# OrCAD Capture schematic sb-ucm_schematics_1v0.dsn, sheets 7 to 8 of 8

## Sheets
7 08. Power: size C; title: SB-UCM    08. Power
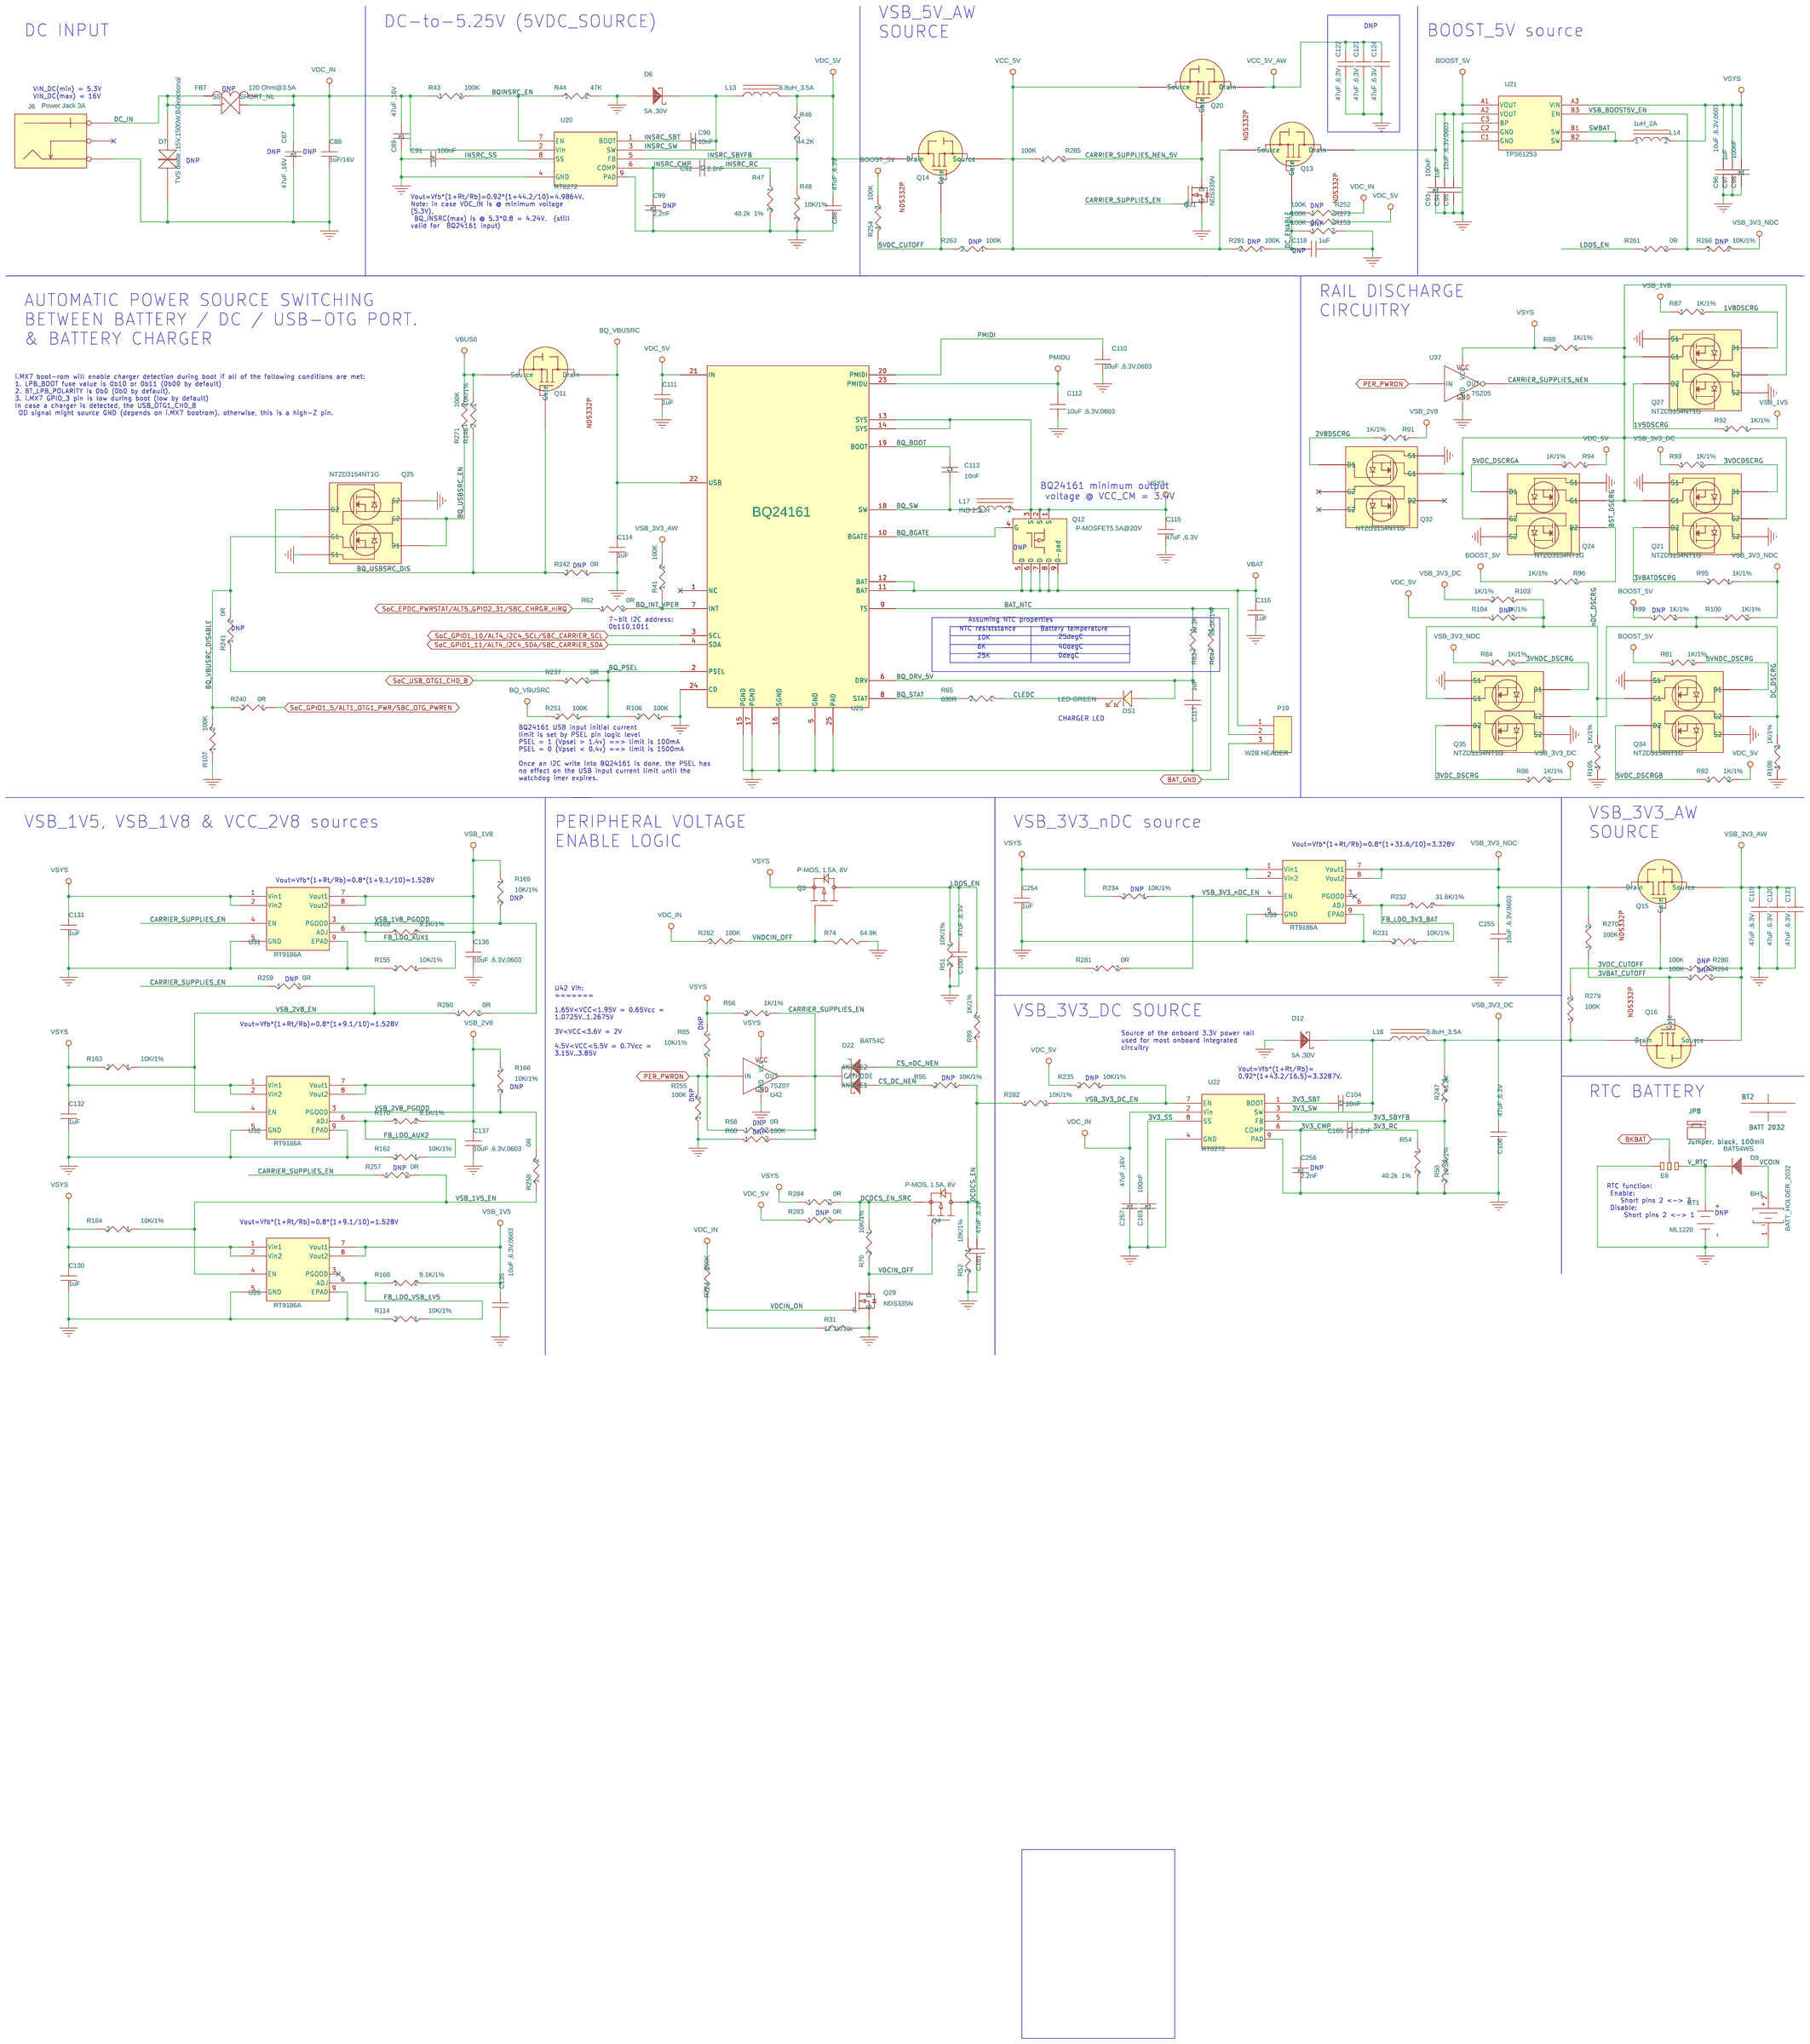
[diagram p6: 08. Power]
8 03. CompuLab CoM/SoM: size C; title: SB-UCM    03. CompuLab CoM/SoM
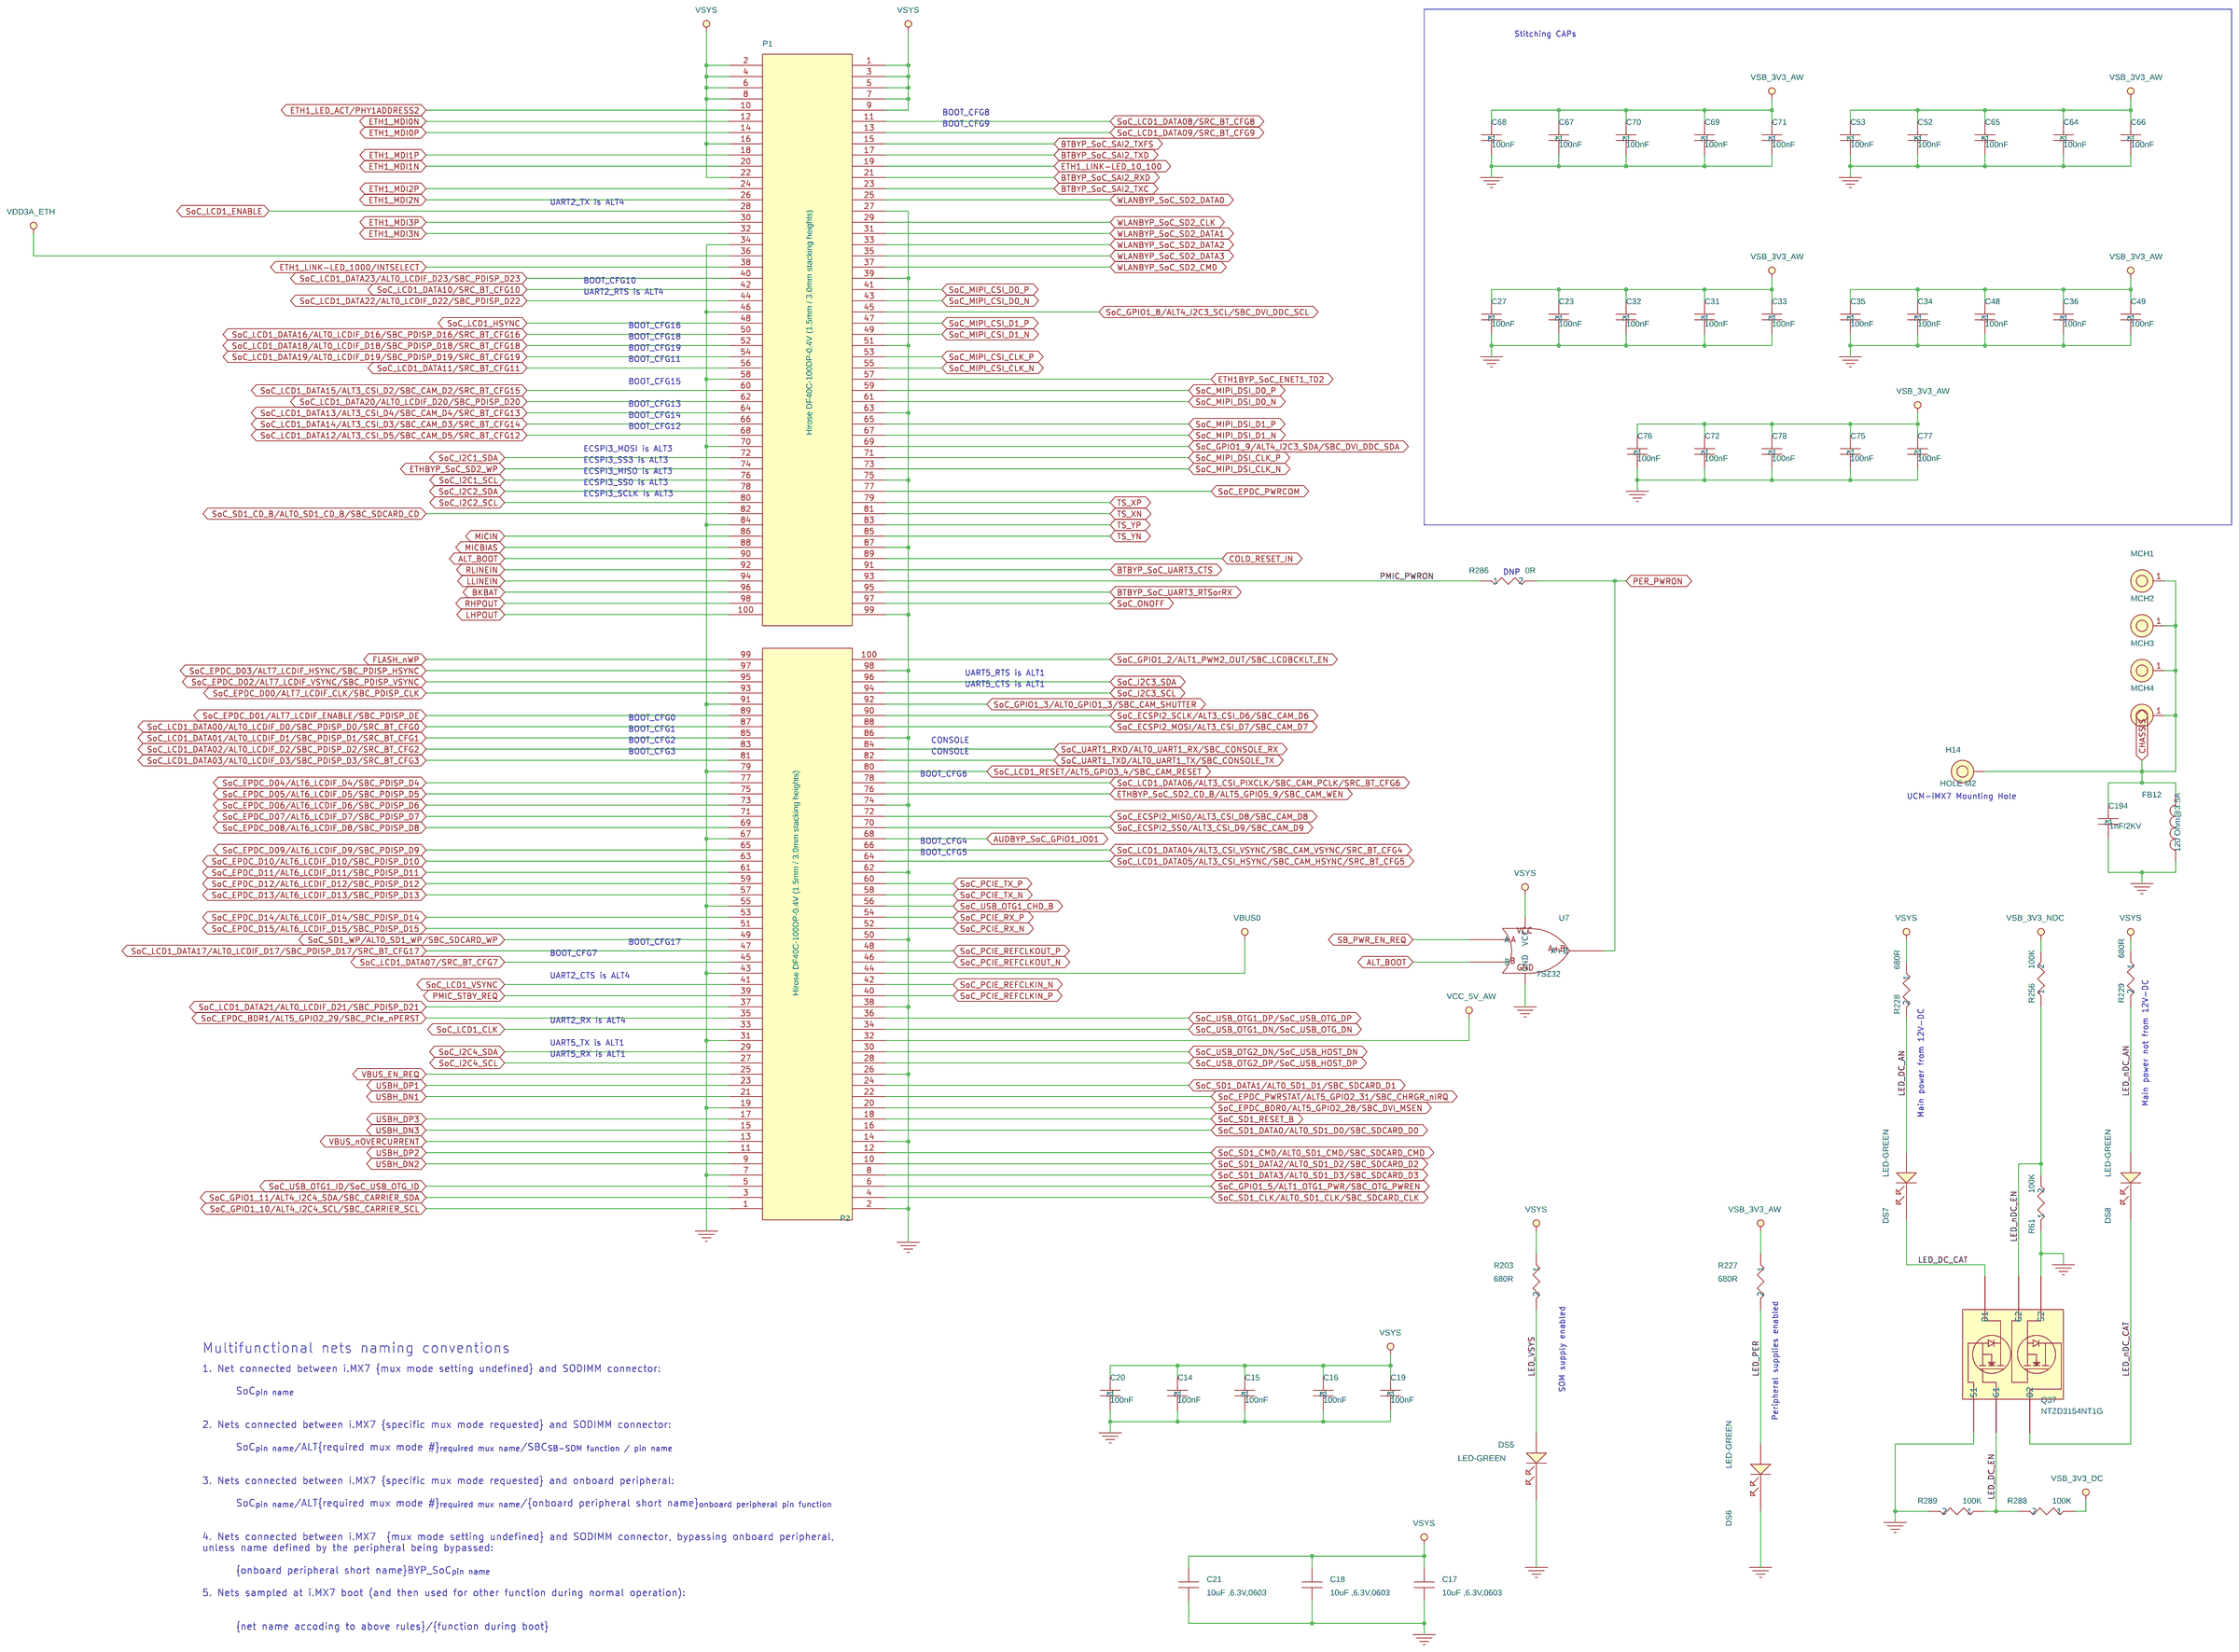
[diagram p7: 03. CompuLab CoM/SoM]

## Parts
sheet 03. CompuLab CoM/SoM
C14  100nF  [RC0402]
C15  100nF  [RC0402]
C16  100nF  [RC0402]
C17  10uF ,6.3V,0603  [C0603-08]
C18  10uF ,6.3V,0603  [C0603-08]
C19  100nF  [RC0402]
C20  100nF  [RC0402]
C21  10uF ,6.3V,0603  [C0603-08]
C23  100nF  [RC0402]
C27  100nF  [RC0402]
C31  100nF  [RC0402]
C32  100nF  [RC0402]
C33  100nF  [RC0402]
C34  100nF  [RC0402]
C35  100nF  [RC0402]
C36  100nF  [RC0402]
C48  100nF  [RC0402]
C49  100nF  [RC0402]
C52  100nF  [RC0402]
C53  100nF  [RC0402]
C64  100nF  [RC0402]
C65  100nF  [RC0402]
C66  100nF  [RC0402]
C67  100nF  [RC0402]
C68  100nF  [RC0402]
C69  100nF  [RC0402]
C70  100nF  [RC0402]
C71  100nF  [RC0402]
C72  100nF  [RC0402]
C75  100nF  [RC0402]
C76  100nF  [RC0402]
C77  100nF  [RC0402]
C78  100nF  [RC0402]
C194  1nF/2KV  [C1812-HV-2]
DS5  LED-GREEN  [LED-1206]
DS6  LED-GREEN  [LED-1206]
DS7  LED-GREEN  [LED-1206]
DS8  LED-GREEN  [LED-1206]
FB12  120 Ohm@3.5A  [FB1206]
H14  HOLE M2  [M2PAD]
MCH1  MechHole  [3,5X6,5]
MCH2  MechHole  [3,5X6,5]
MCH3  MechHole  [3,5X6,5]
MCH4  MechHole  [3,5X6,5]
P1  Hirose DF40C-100DP-0.4V (1.5mm / 3.0mm stacking heights)  [B2B04M2X50R]
P2  Hirose DF40C-100DP-0.4V (1.5mm / 3.0mm stacking heights)  [B2B04M2X50R]
Q37  NTZD3154NT1G  [SOT-563-6]
R61  100K  [RC0402]
R203  680R  [RC0402]
R227  680R  [RC0402]
R228  680R  [RC0402]
R229  680R  [RC0402]
R256  100K  [RC0402]
R286  0R  [RC0402]
R288  100K  [RC0402]
R289  100K  [RC0402]
U7  7SZ32  [SC70]
sheet 08. Power
BH1  BATT_HOLDER_2032  [BattH20mm]
BT1  ML1220  [BT1220SM]
BT2  BATT 2032
C86  47uF ,6.3V  [C0805]
C87  47uF ,16V  [C1210H2_5]
C88  1uF/16V  [RC0402]
C89  47uF ,16V  [C1210H2_5]
C90  10nF  [RC0402]
C91  100nF  [RC0402]
C92  2.2nF  [RC0402]
C93  100nF  [RC0402]
C94  1uF  [RC0402]
C95  10uF ,6.3V,0603  [C0603-08]
C96  10uF ,6.3V,0603  [C0603-08]
C97  1uF  [RC0402]
C98  100nF  [RC0402]
C99  2.2nF  [RC0402]
C100  47uF ,6.3V  [C0805]
C101  47uF ,6.3V  [C0805]
C103  100nF  [RC0402]
C104  10nF  [RC0402]
C105  2.2nF  [RC0402]
C106  47uF ,6.3V  [C0805]
C110  10uF ,6.3V,0603  [C0603-08]
C111  1uF  [RC0402]
C112  10uF ,6.3V,0603  [C0603-08]
C113  10nF  [RC0402]
C114  1uF  [RC0402]
C115  47uF ,6.3V  [C0805]
C116  1uF  [RC0402]
C117  1uF  [RC0402]
C118  1uF  [RC0402]
C119  47uF ,6.3V  [C0805]
C120  47uF ,6.3V  [C0805]
C121  47uF ,6.3V  [C0805]
C122  47uF ,6.3V  [C0805]
C123  47uF ,6.3V  [C0805]
C124  47uF ,6.3V  [C0805]
C130  1uF  [RC0402]
C131  1uF  [RC0402]
C132  1uF  [RC0402]
C135  10uF ,6.3V,0603  [C0603-08]
C136  10uF ,6.3V,0603  [C0603-08]
C137  10uF ,6.3V,0603  [C0603-08]
C254  1uF  [RC0402]
C255  10uF ,6.3V,0603  [C0603-08]
C256  2.2nF  [RC0402]
C257  47uF ,16V  [C1210H2_5]
D6  5A ,30V  [SOD-128]
D7  TVS diode ,15V,1500W,BiDirectional  [DO-214AB]
D9  BAT54WS  [SOD-323]
D12  5A ,30V  [SOD-128]
D22  BAT54C  [SOT23]
DS1  LED-GREEN  [LED-1206]
E8  JP3  [1X3THHDR]
FB7  120 Ohm@3.5A  [FB1206]
J6  Power Jack 3A  [PJ-0210-TH]
JP8  Jumper, black, 100mil  [Shunt/Jumper]
L13  6.8uH_3.5A  [IND8_2x8_2]
L14  1uH_2A  [IND-3x3_5]
L16  6.8uH_3.5A  [IND8_2x8_2]
L17  IND 2.2uH  [IND4_3x4_7SM]
P19  W2B HEADER  [1x3W2B1_5RASM]
Q3  P-MOS, 1.5A, 8V  [SOT23]
Q4  P-MOS, 1.5A, 8V  [SOT23]
Q11  NDS332P  [SOT23]
Q12  P-MOSFET5.5A@20V  [Powerpak1212-8]
Q13  NDS332P  [SOT23]
Q14  NDS332P  [SOT23]
Q15  NDS332P  [SOT23]
Q16  NDS332P  [SOT23]
Q20  NDS332P  [SOT23]
Q21  NTZD3154NT1G  [SOT-563-6]
Q24  NTZD3154NT1G  [SOT-563-6]
Q25  NTZD3154NT1G  [SOT-563-6]
Q27  NTZD3154NT1G  [SOT-563-6]
Q29  NDS335N  [SOT23]
Q31  NDS335N  [SOT23]
Q32  NTZD3154NT1G  [SOT-563-6]
Q34  NTZD3154NT1G  [SOT-563-6]
Q35  NTZD3154NT1G  [SOT-563-6]
R31  12.1K/1%  [RC0402]
R41  100K  [RC0402]
R43  100K  [RC0402]
R44  47K  [RC0402]
R46  44.2K  [RC0402]
R47  40.2k  1%  [RC0402]
R48  10K/1%  [RC0402]
R50  16.5K/1%  [RC0402]
R51  10K/1%  [RC0402]
R52  10K/1%  [RC0402]
R54  40.2k  1%  [RC0402]
R55  10K/1%  [RC0402]
R56  1K/1%  [RC0402]
R58  0R  [RC0402]
R60  100K  [RC0402]
R62  0R  [RC0402]
R63  13.3K  [RC0402]
R64  95.3K/1%  [RC0402]
R65  680R  [RC0402]
R74  64.9K  [RC0402]
R76  10K/1%  [RC0402]
R81  1K/1%  [RC0402]
R82  1K/1%  [RC0402]
R84  1K/1%  [RC0402]
R85  10K/1%  [RC0402]
R86  1K/1%  [RC0402]
R87  1K/1%  [RC0402]
R88  1K/1%  [RC0402]
R89  1K/1%  [RC0402]
R91  1K/1%  [RC0402]
R92  1K/1%  [RC0402]
R93  1K/1%  [RC0402]
R94  1K/1%  [RC0402]
R95  1K/1%  [RC0402]
R96  1K/1%  [RC0402]
R99  1K/1%  [RC0402]
R100  1K/1%  [RC0402]
R103  1K/1%  [RC0402]
R104  1K/1%  [RC0402]
R105  1K/1%  [RC0402]
R106  100K  [RC0402]
R107  100K  [RC0402]
R108  1K/1%  [RC0402]
R114  10K/1%  [RC0402]
R146  10K/1%  [RC0402]
R155  10K/1%  [RC0402]
R162  10K/1%  [RC0402]
R163  10K/1%  [RC0402]
R164  10K/1%  [RC0402]
R165  10K/1%  [RC0402]
R166  10K/1%  [RC0402]
R168  9.1K/1%  [RC0402]
R169  9.1K/1%  [RC0402]
R170  9.1K/1%  [RC0402]
R231  10K/1%  [RC0402]
R232  31.6K/1%  [RC0402]
R234  10K/1%  [RC0402]
R235  10K/1%  [RC0402]
R237  0R  [RC0402]
R240  0R  [RC0402]
R241  0R  [RC0402]
R242  0R  [RC0402]
R247  43.2K  [RC0402]
R251  100K  [RC0402]
R252  100K  [RC0402]
R253  100K  [RC0402]
R254  100K  [RC0402]
R255  100K  [RC0402]
R257  0R  [RC0402]
R258  0R  [RC0402]
R259  0R  [RC0402]
R260  0R  [RC0402]
R261  0R  [RC0402]
R262  100K  [RC0402]
R263  100K  [RC0402]
R264  100K  [RC0402]
R266  10K/1%  [RC0402]
R270  100K  [RC0402]
R271  100K  [RC0402]
R273  100K  [RC0402]
R274  100K  [RC0402]
R279  100K  [RC0402]
R280  100K  [RC0402]
R281  0R  [RC0402]
R282  10K/1%  [RC0402]
R283  0R  [RC0402]
R284  0R  [RC0402]
R285  100K  [RC0402]
R291  100K  [RC0402]
S5  SHORT_NL  [JUMPER-VIA_1]
U20  RT8272  [PSOP-8-2X2]
U21  TPS61253  [BGA-9-04-1.4x1.3]
U22  RT8272  [PSOP-8-2X2]
U25  BQ24161  [MO-220VGGD-8]
U26  RT9186A  [DFN3x3-8]
U31  RT9186A  [DFN3x3-8]
U32  RT9186A  [DFN3x3-8]
U37  7SZ05  [SC70]
U39  RT9186A  [DFN3x3-8]
U42  7SZ07  [SC70]

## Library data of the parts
C14 = 100nF,_10V,_X7R,_10%,_0402_21: CLABCONF0: = SB-UCM
C15 = 100nF,_10V,_X7R,_10%,_0402_23: CLABCONF0: = SB-UCM
C16 = 100nF,_10V,_X7R,_10%,_0402_27: CLABCONF0: = SB-UCM
C17 C95 = 10uF,6.3V,0603,20%X5R_1: CLABCONF0: = SB-UCM
C18 = 10uF,6.3V,0603,20%X5R_2: CLABCONF0: = SB-UCM
C19 C103 = 100nF,_10V,_X7R,_10%,_0402_2: CLABCONF0: = SB-UCM
C20 = 100nF,_10V,_X7R,_10%,_0402_19: CLABCONF0: = SB-UCM
C21 C96 = 10uF,6.3V,0603,20%X5R: CLABCONF0: = SB-UCM
C23 = 100nF,_10V,_X7R,_10%,_0402_10: CLABCONF0: = SB-UCM
C27 = 100nF,_10V,_X7R,_10%,_0402_13: CLABCONF0: = SB-UCM
C31 = 100nF,_10V,_X7R,_10%,_0402_15: CLABCONF0: = SB-UCM
C32 = 100nF,_10V,_X7R,_10%,_0402_16: CLABCONF0: = SB-UCM
C33 = 100nF,_10V,_X7R,_10%,_0402_17: CLABCONF0: = SB-UCM
C34 C93 = 100nF,_10V,_X7R,_10%,_0402_1: CLABCONF0: = SB-UCM
C35 = 100nF,_10V,_X7R,_10%,_0402_5: CLABCONF0: = SB-UCM
C36 = 100nF,_10V,_X7R,_10%,_0402_8: CLABCONF0: = SB-UCM
C48 = 100nF,_10V,_X7R,_10%,_0402_12: CLABCONF0: = SB-UCM
C49 = 100nF,_10V,_X7R,_10%,_0402_14: CLABCONF0: = SB-UCM
C52 = 100nF,_10V,_X7R,_10%,_0402_25: CLABCONF0: = SB-UCM
C53 = 100nF,_10V,_X7R,_10%,_0402_29: CLABCONF0: = SB-UCM
C64 = 100nF,_10V,_X7R,_10%,_0402_4: CLABCONF0: = SB-UCM
C65 = 100nF,_10V,_X7R,_10%,_0402_7: CLABCONF0: = SB-UCM
C66 = 100nF,_10V,_X7R,_10%,_0402_11: CLABCONF0: = SB-UCM
C67 = 100nF,_10V,_X7R,_10%,_0402_24: CLABCONF0: = SB-UCM
C68 = 100nF,_10V,_X7R,_10%,_0402_28: CLABCONF0: = SB-UCM
C69 C98 = 100nF,_10V,_X7R,_10%,_0402_3: CLABCONF0: = SB-UCM
C70 = 100nF,_10V,_X7R,_10%,_0402_6: CLABCONF0: = SB-UCM
C71 = 100nF,_10V,_X7R,_10%,_0402_9: CLABCONF0: = SB-UCM
C72 = 100nF,_10V,_X7R,_10%,_0402_18: CLABCONF0: = SB-UCM
C75 = 100nF,_10V,_X7R,_10%,_0402_20: CLABCONF0: = SB-UCM
C76 = 100nF,_10V,_X7R,_10%,_0402_22: CLABCONF0: = SB-UCM
C77 = 100nF,_10V,_X7R,_10%,_0402_26: CLABCONF0: = SB-UCM
C78 C91 = 100nF,_10V,_X7R,_10%,_0402: CLABCONF0: = SB-UCM
C194 = 1nF,_2KV,SMD_1812,_X7R,_10%: CLABCONF0: = SB-UCM
DS1 DS5-DS8 = LED-GREEN_1206_3: CLABCONF0: = SB-UCM
FB12 = Ferrite_bead_,_120_Ohm@3A: CLABCONF0: = SB-UCM
H14 = Hole,_Plated,_M2,_5mm._ext.: CLABCONF0: DNP
MCH1-MCH4 = Mechanical_Hole: CLABCONF0: DNP; P/N: 3X6HOL
P1 P2 = Hirose_DF40C-100DP-0.4V: CLABCONF0: = SB-UCM; P/N: 182K10004S
Q21 Q24 Q25 Q27 Q32 Q34 Q35 Q37 = MOSFET_N_DUAL_0_0.4A_20V: CLABCONF0: = SB-UCM
R61 R274 = 100K,_0402_2: CLABCONF0: = SB-UCM; P/N: 161C10031S
R203 = 47K,_0402_1: CLABCONF0: = SB-UCM; P/N: 161C68001S
R65 R227 = 47K,_0402: CLABCONF0: = SB-UCM; P/N: 161C68001S
R228 = 47K,_0402_2: CLABCONF0: = SB-UCM; P/N: 161C68001S
R229 = 47K,_0402_3: CLABCONF0: = SB-UCM; P/N: 161C68001S
R256 R291 = 100K,_0402_3: CLABCONF0: = SB-UCM; P/N: 161C10031S
R259 R286 = 0R,_0402: CLABCONF0: DNP
R288 = 100K,_0402_1: CLABCONF0: = SB-UCM; P/N: 161C10031S
R270 R289 = 100K,_0402: CLABCONF0: = SB-UCM; P/N: 161C10031S
U7 = 7SZ32_OR_sgl_SC70: CLABCONF0: = SB-UCM
BH1 = BATT_HOLDER_0: CLABCONF0: = SB-UCM
BT1 = ML1020: CLABCONF0: DNP
BT2 = BATT_2032: CLABCONF0: = SB-UCM
C86 = 47uF,6.3V,X5R_3: CLABCONF0: = SB-UCM
C87 = Cap.,_47uF,_16V,_X5R_2: CLABCONF0: DNP
C88 = 1uF,16V,0402: CLABCONF0: = SB-UCM
C89 = Cap.,_47uF,_16V,_X5R_1: CLABCONF0: = SB-UCM
C90 = 10nF,_25V,_X7R,_10%,_0402: CLABCONF0: = SB-UCM
C92 = 2.2nF,_50V,_X7R,_10%,_0402_3: CLABCONF0: = SB-UCM
C94 C97 = Cap_1uF,X5R,6.3V,0402: CLABCONF0: = SB-UCM
C99 = 2.2nF,_50V,_X7R,_10%,_0402_1: CLABCONF0: DNP
C100 = 47uF,6.3V,X5R_2: CLABCONF0: = SB-UCM
C101 = 47uF,6.3V,X5R_1: CLABCONF0: = SB-UCM
C104 = 10nF,_25V,_X7R,_10%,_0402_1: CLABCONF0: = SB-UCM
C105 = 2.2nF,_50V,_X7R,_10%,_0402_2: CLABCONF0: = SB-UCM
C106 = 47uF,6.3V,X5R: CLABCONF0: = SB-UCM
C110 = 10uF,6.3V,0603,X5R: CLABCONF0: = SB-UCM
C111 C114 C116 C117 C130-C132 C254 = 1uF,X5R,6.3V,0402: CLABCONF0: = SB-UCM
C112 = 10uF,6.3V,0603,X5R_1: CLABCONF0: = SB-UCM
C113 = 10nF,_25V,_X7R,_10%,_0402_2: CLABCONF0: = SB-UCM
C115 = Cap.,47uF,6.3V,X5R_1: CLABCONF0: = SB-UCM
C118 = 1uF,X5R,6.3V,0402: CLABCONF0: DNP
C119 = Cap.,47uF,6.3V,X5R_5: CLABCONF0: = SB-UCM
C120 = Cap.,47uF,6.3V,X5R_6: CLABCONF0: = SB-UCM
C121 = Cap.,47uF,6.3V,X5R_4: CLABCONF0: = SB-UCM
C122 = Cap.,47uF,6.3V,X5R_2: CLABCONF0: DNP
C123 = Cap.,47uF,6.3V,X5R_3: CLABCONF0: DNP
C124 = Cap.,47uF,6.3V,X5R: CLABCONF0: DNP
C135-C137 C255 = 10uF,6_0.3V,0603,20%X5R: CLABCONF0: = SB-UCM
C256 = 2.2nF,_50V,_X7R,_10%,_0402: CLABCONF0: DNP
C257 = Cap.,_47uF,_16V,_X5R: CLABCONF0: = SB-UCM
D6 D12 = Diode_Shotky,5A,30V: CLABCONF0: = SB-UCM
D7 = Diode_,TVS_,15V,1500W_0: CLABCONF0: DNP; P/N: 132D00150S
D9 = BAT54WS_0: CLABCONF0: = SB-UCM
D22 = BAT54C: CLABCONF0: = SB-UCM
E8 = HDR_1x3_100MIL_TH_JUMPER: CLABCONF0: = SB-UCM
FB7 = Ferrite_bead_,_120_Ohm@3A: CLABCONF0: DNP
J6 = Conn._DC,_TH,_3A: CLABCONF0: = SB-UCM
JP8 = Jumper,_black,_100mil: CLABCONF0: = SB-UCM
L13 L16 = IND_6.8uH_3.5A: CLABCONF0: = SB-UCM; P/N: 147A6R801S
L14 = IND_DELTA_MPL73-2R2_2.2uH_14A_1: CLABCONF0: = SB-UCM; Isat: 7; Linit: 3.3uH; P/N: 147A1R001S
L17 = IND_DELTA_MPL73-2R2_2.2uH_14A: CLABCONF0: = SB-UCM; Group: Always; Isat: 5A; P/N: 147A2R204S
P19 = TMP_142956: CLABCONF0: = SB-UCM
Q3 Q4 = P-MOS,_1.5A,_8V: CLABCONF0: = SB-UCM
Q11 Q13-Q16 Q20 = NDS332P: CLABCONF0: = SB-UCM
Q12 = MOSFET_P,_5.5A_20V: CLABCONF0: DNP
Q29 Q31 = N-MOSFET,NDS335N,100mOhm@2.5V: CLABCONF0: = SB-UCM
R31 = 12_0.1K,1%,0402,1_16W: CLABCONF0: = SB-UCM
R41 = 100K,_0402_7: CLABCONF0: = SB-UCM; P/N: 161C10031S
R43 = 100K,_0402_13: CLABCONF0: = SB-UCM; P/N: 161C10031S
R44 = 47K,_0402_1: CLABCONF0: = SB-UCM
R46 = 100K,_0402_4: CLABCONF0: = SB-UCM; P/N: 161C44221S
R47 = 40.2k_,1%_1: CLABCONF0: = SB-UCM
R48 = 10K,1%,0402,1_16W_11: CLABCONF0: = SB-UCM
R50 = 10K,1%,0402,1_16W_8: CLABCONF0: = SB-UCM; P/N: 161C16521S
R51 = 10K,1%,0402,1_16W_6: CLABCONF0: = SB-UCM
R52 = 10K,1%,0402,1_16W_1: CLABCONF0: = SB-UCM
R54 = 40.2k_,1%: CLABCONF0: = SB-UCM
R55 = 10K,1%,0402,1_16W_15: CLABCONF0: DNP
R56 = 1K,1%,0402,1_16W_11: CLABCONF0: = SB-UCM; Group: CAN
R58 = 0R,_0402_10: CLABCONF0: DNP
R60 = 100K,_0402_1: CLABCONF0: DNP; P/N: 161C10031S
R62 = 0R,_0402_2: CLABCONF0: = SB-UCM
R63 = 13.3K,_0402_tmp: CLABCONF0: = SB-UCM; P/N: 161C13321S
R64 = 4.99K,1%,0402,1_16W: CLABCONF0: = SB-UCM; P/N: 161C95321S
R74 = 64.9K,1%,0402: CLABCONF0: = SB-UCM; P/N: 161C64921S
R76 = 10K,1%,0402,1_16W_17: CLABCONF0: = SB-UCM
R81 = 1K,1%,0402,1_16W_3: CLABCONF0: = SB-UCM; Group: CAN
R82 = 1K,1%,0402,1_16W_2: CLABCONF0: = SB-UCM; Group: CAN
R84 = 1K,1%,0402,1_16W_15: CLABCONF0: = SB-UCM; Group: CAN
R85 = 10K,1%,0402,1_16W_19: CLABCONF0: DNP
R86 = 1K,1%,0402,1_16W_12: CLABCONF0: = SB-UCM; Group: CAN
R87 = 1K,1%,0402,1_16W_5: CLABCONF0: = SB-UCM; Group: CAN
R88 = 1K,1%,0402,1_16W_10: CLABCONF0: = SB-UCM; Group: CAN
R89 = 1K,1%,0402,1_16W_4: CLABCONF0: = SB-UCM; Group: CAN
R91 = 1K,1%,0402,1_16W_9: CLABCONF0: = SB-UCM; Group: CAN
R92 = 1K,1%,0402,1_16W_6: CLABCONF0: = SB-UCM; Group: CAN
R93 = 1K,1%,0402,1_16W_14: CLABCONF0: = SB-UCM; Group: CAN
R94 = 1K,1%,0402,1_16W_7: CLABCONF0: = SB-UCM; Group: CAN
R95 = 1K,1%,0402,1_16W_19: CLABCONF0: = SB-UCM; Group: CAN
R96 = 1K,1%,0402,1_16W_18: CLABCONF0: = SB-UCM; Group: CAN
R99 = 1K,1%,0402,1_16W_17: CLABCONF0: DNP; Group: CAN
R100 = 1K,1%,0402,1_16W_1: CLABCONF0: = SB-UCM; Group: CAN
R103 = 1K,1%,0402,1_16W_8: CLABCONF0: = SB-UCM; Group: CAN
R104 = 1K,1%,0402,1_16W_16: CLABCONF0: DNP; Group: CAN
R105 = 1K,1%,0402,1_16W_13: CLABCONF0: = SB-UCM; Group: CAN
R106 = 100K,_0402_14: CLABCONF0: = SB-UCM; P/N: 161C10031S
R107 = 100K,_0402_15: CLABCONF0: = SB-UCM; P/N: 161C10031S
R108 = 1K,1%,0402,1_16W: CLABCONF0: = SB-UCM; Group: CAN
R114 = 10K,1%,0402,1_16W_12: CLABCONF0: = SB-UCM
R146 = 10K,1%,0402,1_16W_14: CLABCONF0: = SB-UCM
R155 = 10K,1%,0402,1_16W_3: CLABCONF0: = SB-UCM
R162 = 10K,1%,0402,1_16W_4: CLABCONF0: = SB-UCM
R163 = 10K,1%,0402,1_16W_16: CLABCONF0: = SB-UCM
R164 = 10K,1%,0402,1_16W_10: CLABCONF0: = SB-UCM
R165 = 10K,1%,0402,1_16W_18: CLABCONF0: DNP
R166 = 10K,1%,0402,1_16W_5: CLABCONF0: DNP
R168 = 953R,1%,0402,1_16W_0_2: CLABCONF0: = SB-UCM; P/N: 161C91011S
R169 = 953R,1%,0402,1_16W_0_1: CLABCONF0: = SB-UCM; P/N: 161C91011S
R170 = 953R,1%,0402,1_16W_0: CLABCONF0: = SB-UCM; P/N: 161C91011S
R231 = 10K,1%,0402,1_16W_7: CLABCONF0: = SB-UCM
R232 = 953R,1%,0402,1_16W_0_3: CLABCONF0: = SB-UCM; P/N: 161C31621S
R234 = 10K,1%,0402,1_16W_2: CLABCONF0: DNP
R235 = 10K,1%,0402,1_16W: CLABCONF0: DNP
R237 = 0R,_0402_1: CLABCONF0: = SB-UCM
R240 = 0R,_0402_3: CLABCONF0: = SB-UCM
R241 = 0R,_0402_13: CLABCONF0: DNP
R242 = 0R,_0402_5: CLABCONF0: DNP
R247 = 100K,_0402_11: CLABCONF0: = SB-UCM; P/N: 161C43221S
R251 = 100K,_0402_22: CLABCONF0: = SB-UCM; P/N: 161C10031S
R252 = 100K,_0402_20: CLABCONF0: DNP; P/N: 161C10031S
R253 = 100K,_0402_12: CLABCONF0: DNP; P/N: 161C10031S
R254 = 100K,_0402_8: CLABCONF0: = SB-UCM; P/N: 161C10031S
R255 = 100K,_0402_10: CLABCONF0: DNP; P/N: 161C10031S
R257 = 0R,_0402_9: CLABCONF0: DNP
R258 = 0R,_0402_4: CLABCONF0: = SB-UCM
R260 = 0R,_0402_12: CLABCONF0: = SB-UCM
R261 = 0R,_0402_6: CLABCONF0: = SB-UCM
R262 = 100K,_0402_19: CLABCONF0: = SB-UCM; P/N: 161C10031S
R263 = 100K,_0402_9: CLABCONF0: DNP; P/N: 161C10031S
R264 = 100K,_0402_21: CLABCONF0: DNP; P/N: 161C10031S
R266 = 10K,1%,0402,1_16W_9: CLABCONF0: DNP
R271 = 100K,_0402_5: CLABCONF0: = SB-UCM; P/N: 161C10031S
R273 = 100K,_0402_6: CLABCONF0: = SB-UCM; P/N: 161C10031S
R279 = 100K,_0402_16: CLABCONF0: = SB-UCM; P/N: 161C10031S
R280 = 100K,_0402_17: CLABCONF0: DNP; P/N: 161C10031S
R281 = 0R,_0402_8: CLABCONF0: = SB-UCM
R282 = 10K,1%,0402,1_16W_13: CLABCONF0: = SB-UCM
R283 = 0R,_0402_11: CLABCONF0: DNP
R284 = 0R,_0402_7: CLABCONF0: = SB-UCM
R285 = 100K,_0402_18: CLABCONF0: = SB-UCM; P/N: 161C10031S
S5 = MISC_SHORT_NL: CLABCONF0: DNP
U20 U22 = RT8272,Converter,3A,24V: CLABCONF0: = SB-UCM
U21 = TPS61253: CLABCONF0: = SB-UCM; P/N: 123C15200S
U25 = ISL9011_DUAL_LDO_11: CLABCONF0: = SB-UCM; P/N: 123D4R202S
U26 U31 U32 U39 = RT9186A,LDO_,2.5-5_0.5V,500mA: CLABCONF0: = SB-UCM
U37 = 7SZ05_sgl_OD_inverter,_SC70: CLABCONF0: = SB-UCM
U42 = 7SZ07D,_buffer: CLABCONF0: = SB-UCM; P/N: 106D20070S

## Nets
1V5DSCRG: Q27.3(D2) R92.2
1V8DSCRG: Q27.6(D1) R87.2
2V8DSCRG: Q32.6(D1) R91.2
3V3_CMP: C105.1 C256.1 U22.6(COMP)
3V3_RC: C105.2 R54.1
3V3_SBT: C104.1 U22.1(BOOT)
3V3_SBYFB: R50.1 R247.2 U22.5(FB)
3V3_SS: C103.1 U22.8(SS)
3V3_SW: C104.2 D12.CATHODE L16.1 U22.3(SW)
3VBAT_CUTOFF: Q16.1(Gate) R264.1 R270.1
3VBATDSCRG: Q21.3(D2) R95.2
3VDC_CUTOFF: Q15.1(Gate) R279.2 R280.1
3VDC_DSCRG: Q35.3(D2) R86.1
3VDCDSCRG: Q21.6(D1) R93.2
3VNDC_DSCRG: Q35.6(D1) R84.2
5VDC_CUTOFF: Q14.1(Gate) R254.1 R263.2
5VDC_DSCRGA: Q24.6(D1) R94.2
5VDC_DSCRGB: Q34.3(D2) R82.1
5VNDC_DSCRG: Q34.6(D1) R81.2
GND: BH1.1(MINUS) BT1.2(NEG) C14.2 C15.2 C16.2 C17.1 C18.1 C19.2 C20.2 C21.1 C23.2 C27.2 C31.2 C32.2 C33.2 C34.2 C35.2 C36.2 C48.2 C49.2 C52.2 C53.2 C64.2 C65.2 C66.2 C67.2 C68.2 C69.2 C70.2 C71.2 C72.2 C75.2 C76.2 C77.2 C78.2 C86.2 C87.2 C88.2 C89.2 C91.2 C93.2 C94.2 C95.2 C96.2 C97.2 C98.2 C99.2 C100.2 C101.2 C103.2 C106.2 C110.1 C111.2 C112.1 C114.2 C115.2 C116.2 C117.2 C118.2 C119.2 C120.2 C121.2 C122.2 C123.2 C124.2 C130.2 C131.2 C132.2 C135.2 C136.2 C137.2 C194.2 C254.2 C255.2 C256.2 C257.2 D6.ANODE D7.ANODE D12.ANODE DS5.CATHODE DS6.CATHODE E8.1 FB12.1 J6.3 P1.27 P1.34 P1.39 P1.46 P1.51 P1.58 P1.63 P1.70 P1.75 P1.84 P1.87 P1.99 P2.2 P2.7 P2.14 P2.19 P2.26 P2.31 P2.38 P2.43 P2.50 P2.55 P2.62 P2.67 P2.74 P2.79 P2.86 P2.91 P2.98 Q21.1(S1) Q21.4(S2) Q24.1(S1) Q24.4(S2) Q25.1(S1) Q25.4(S2) Q27.1(S1) Q27.4(S2) Q29.2(S) Q31.2(S) Q32.1(S1) Q34.1(S1) Q34.4(S2) Q35.1(S1) Q35.4(S2) Q37.1(S1) Q37.4(S2) R31.1 R44.2 R47.2 R48.2 R50.2 R51.2 R52.2 R54.2 R60.1 R61.1 R64.2 R74.1 R105.1 R106.1 R107.1 R108.1 R114.2 R155.2 R162.2 R231.2 R242.1 R253.2 R255.1 R289.2 U7.3(GND) U20.4(GND) U20.9(PAD) U21.C1(GND) U21.C2(GND) U21.C3(BP) U22.4(GND) U22.9(PAD) U25.5(GND) U25.15(PGND) U25.16(SGND) U25.17(PGND) U25.24(CD) U25.25(PAD) U26.5(GND) U26.9(EPAD) U31.5(GND) U31.9(EPAD) U32.5(GND) U32.9(EPAD) U37.3(GND) U39.5(GND) U39.9(EPAD) U42.3(GND) ; also on sheet 1 4 5 6
VBAT: C116.1 P19.1 Q12.5(D) Q12.6(D) Q12.7(D) Q12.8(D) Q12.9(D-pad) U25.11(BAT) U25.12(BAT) ; also on sheet 6
VBUS0: P2.44 Q11.2(Source) R146.1 R271.2 ; also on sheet 6
VBUS_EN_REQ: P2.25 ; also on sheet 6
VBUS_nOVERCURRENT: P2.13 ; also on sheet 6
VCC_5V: Q13.2(Source) Q14.2(Source) Q20.2(Source) R263.1 R285.1 R291.2
VCC_5V_AW: C122.1 C123.1 C124.1 P2.32 Q20.3(Drain) ; also on sheet 1 4 5 6
VDD3A_ETH: P1.36 ; also on sheet 1
ALT_BOOT: P1.90 U7.2(B) ; also on sheet 4
AUDBYP_SoC_GPIO1_IO01: P2.68 ; also on sheet 1
BAT_GND: P19.3 ; also on sheet 6
BAT_NTC: P19.2 R63.1 R64.1 U25.9(TS)
BKBAT: E8.2 P1.96
BOOST_5V: C93.1 C94.1 C95.1 Q13.3(Drain) R81.1 R96.1 R99.1 R254.2 U21.A1(VOUT) U21.A2(VOUT) ; also on sheet 4 5 6
BQ_BGATE: Q12.4(G) U25.10(BGATE)
BQ_BOOT: C113.2 U25.19(BOOT)
BQ_DRV_5V: C117.1 DS1.ANODE R63.2 U25.6(DRV)
BQ_INT_VPER: R41.1 R62.2 U25.7(INT)
BQ_PSEL: R106.2 R237.2 R241.1 R251.1 U25.2(PSEL)
BQ_STAT: R65.2 U25.8(STAT)
BQ_SW: C113.1 L17.1 U25.18(SW)
BQ_USBSRC_DIS: Q11.1(Gate) Q25.3(D2) R146.2 R242.2
BQ_USBSRC_EN: Q25.5(G2) Q25.6(D1) R271.1
BQ_VBUSRC: C114.1 Q11.3(Drain) R251.2 U25.22(USB) ; also on sheet 6
BQ_VBUSRC_DISABLE: Q25.2(G1) R107.2 R240.2 R241.2
BQINSRC_EN: R43.2 R44.1 U20.7(EN)
BST_DSCRG: Q24.3(D2) R96.2
BTBYP_SoC_SAI2_RXD: P1.21 ; also on sheet 1
BTBYP_SoC_SAI2_TXC: P1.23 ; also on sheet 1
BTBYP_SoC_SAI2_TXD: P1.17 ; also on sheet 1
BTBYP_SoC_SAI2_TXFS: P1.15 ; also on sheet 1
BTBYP_SoC_UART3_CTS: P1.91 ; also on sheet 1
BTBYP_SoC_UART3_RTSorRX: P1.95 ; also on sheet 1
CARRIER_SUPPLIES_EN: D22.3(CATHODE) Q31.1(G) R56.1 R58.2 R60.2 R257.1 R259.1 U31.4(EN) U42.4(OUT)
CARRIER_SUPPLIES_NEN: Q21.2(G1) Q21.5(G2) Q24.2(G1) Q24.5(G2) Q27.2(G1) Q27.5(G2) Q32.2(G1) R88.1 U37.4(OUT)
CARRIER_SUPPLIES_NEN_5V: Q20.1(Gate) Q31.3(D) R285.2
CHASSIS: C194.1 FB12.2 H14.1 MCH1.1 MCH2.1 MCH3.1 MCH4.1 ; also on sheet 1 4 5 6
CLEDC: DS1.CATHODE R65.1
COLD_RESET_IN: P1.89 ; also on sheet 4
CS_DC_NEN: D22.1(ANODE1) R55.2
CS_nDC_NEN: D22.2(ANODE2) R89.1
DC_DSCRG: Q34.5(G2) Q35.5(G2) R99.2 R100.1 R108.2
DC_ENABLE: C118.1 Q13.1(Gate) R252.1 R253.1 R273.1 R291.1
DC_IN: D7.CATHODE FB7.1 J6.1 S5.1
DCDCS_EN: C101.1 Q4.3(D) R52.1 R55.1 R282.1
DCDCS_EN_SRC: Q4.2(S) R76.1 R283.2 R284.2
ETH1_LED_ACT/PHY1ADDRESS2: P1.10 ; also on sheet 1
ETH1_LINK-LED_10_100: P1.19 ; also on sheet 1
ETH1_LINK-LED_1000/INTSELECT: P1.38 ; also on sheet 1
ETH1_MDI0N: P1.12 ; also on sheet 1
ETH1_MDI0P: P1.14 ; also on sheet 1
ETH1_MDI1N: P1.20 ; also on sheet 1
ETH1_MDI1P: P1.18 ; also on sheet 1
ETH1_MDI2N: P1.26 ; also on sheet 1
ETH1_MDI2P: P1.24 ; also on sheet 1
ETH1_MDI3N: P1.32 ; also on sheet 1
ETH1_MDI3P: P1.30 ; also on sheet 1
ETH1BYP_SoC_ENET1_TD2: P1.57 ; also on sheet 1
ETHBYP_SoC_SD2_CD_B/ALT5_GPIO5_9/SBC_CAM_WEN: P2.76 ; also on sheet 1
ETHBYP_SoC_SD2_WP: P1.74 ; also on sheet 1
FB_LDO_3V3_BAT: R231.1 R232.1 U39.6(ADJ)
FB_LDO_AUX1: R155.1 R169.1 U31.6(ADJ)
FB_LDO_AUX2: R162.1 R170.1 U32.6(ADJ)
FB_LDO_VSB_1V5: R114.1 R168.1 U26.6(ADJ)
FLASH_nWP: P2.99 ; also on sheet 4
INSRC_CMP: C92.1 C99.1 U20.6(COMP)
INSRC_RC: C92.2 R47.1
INSRC_SBT: C90.1 U20.1(BOOT)
INSRC_SBYFB: R46.2 R48.1 U20.5(FB)
INSRC_SS: C91.1 U20.8(SS)
INSRC_SW: C90.2 D6.CATHODE L13.1 U20.3(SW)
LDOS_EN: C100.1 Q3.3(D) R51.1 R89.2 R261.1 R281.1
LED_DC_AN: DS7.ANODE R228.2
LED_DC_CAT: DS7.CATHODE Q37.6(D1)
LED_DC_EN: Q37.2(G1) R288.2 R289.1
LED_nDC_AN: DS8.ANODE R229.2
LED_nDC_CAT: DS8.CATHODE Q37.3(D2)
LED_nDC_EN: Q37.5(G2) R61.2 R256.1
LED_PER: DS6.ANODE R227.2
LED_VSYS: DS5.ANODE R203.2
LHPOUT: P1.100 ; also on sheet 6
LLINEIN: P1.94 ; also on sheet 6
MICBIAS: P1.88 ; also on sheet 6
MICIN: P1.86 ; also on sheet 6
nDC_DSCRG: Q34.2(G1) Q35.2(G1) R103.1 R104.2 R105.2
PER_PWRON: R58.1 R85.2 R255.2 R286.2 U7.4(A+B) U37.2(IN) U42.2(IN)
PMIC_PWRON: P1.93 R286.1
PMIC_STBY_REQ: P2.39 ; also on sheet 1
PMIDI: C110.2 U25.20(PMIDI)
PMIDU: C112.2 U25.23(PMIDU) ; also on sheet 6
RHPOUT: P1.98 ; also on sheet 6
RLINEIN: P1.92 ; also on sheet 6
SB_PWR_EN_REQ: U7.1(A) ; also on sheet 1
SoC_ECSPI2_MISO/ALT3_CSI_D8/SBC_CAM_D8: P2.72 ; also on sheet 1
SoC_ECSPI2_MOSI/ALT3_CSI_D7/SBC_CAM_D7: P2.88 ; also on sheet 1
SoC_ECSPI2_SCLK/ALT3_CSI_D6/SBC_CAM_D6: P2.90 ; also on sheet 1
SoC_ECSPI2_SS0/ALT3_CSI_D9/SBC_CAM_D9: P2.70 ; also on sheet 1
SoC_EPDC_BDR0/ALT5_GPIO2_28/SBC_DVI_MSEN: P2.20 ; also on sheet 1 5
SoC_EPDC_BDR1/ALT5_GPIO2_29/SBC_PCIe_nPERST: P2.35 ; also on sheet 1
SoC_EPDC_D00/ALT7_LCDIF_CLK/SBC_PDISP_CLK: P2.93 ; also on sheet 5
SoC_EPDC_D01/ALT7_LCDIF_ENABLE/SBC_PDISP_DE: P2.89 ; also on sheet 5
SoC_EPDC_D02/ALT7_LCDIF_VSYNC/SBC_PDISP_VSYNC: P2.95 ; also on sheet 5
SoC_EPDC_D03/ALT7_LCDIF_HSYNC/SBC_PDISP_HSYNC: P2.97 ; also on sheet 5
SoC_EPDC_D04/ALT6_LCDIF_D4/SBC_PDISP_D4: P2.77 ; also on sheet 5
SoC_EPDC_D05/ALT6_LCDIF_D5/SBC_PDISP_D5: P2.75 ; also on sheet 5
SoC_EPDC_D06/ALT6_LCDIF_D6/SBC_PDISP_D6: P2.73 ; also on sheet 5
SoC_EPDC_D07/ALT6_LCDIF_D7/SBC_PDISP_D7: P2.71 ; also on sheet 5
SoC_EPDC_D08/ALT6_LCDIF_D8/SBC_PDISP_D8: P2.69 ; also on sheet 5
SoC_EPDC_D09/ALT6_LCDIF_D9/SBC_PDISP_D9: P2.65 ; also on sheet 5
SoC_EPDC_D10/ALT6_LCDIF_D10/SBC_PDISP_D10: P2.63 ; also on sheet 5
SoC_EPDC_D11/ALT6_LCDIF_D11/SBC_PDISP_D11: P2.61 ; also on sheet 5
SoC_EPDC_D12/ALT6_LCDIF_D12/SBC_PDISP_D12: P2.59 ; also on sheet 5
SoC_EPDC_D13/ALT6_LCDIF_D13/SBC_PDISP_D13: P2.57 ; also on sheet 5
SoC_EPDC_D14/ALT6_LCDIF_D14/SBC_PDISP_D14: P2.53 ; also on sheet 5
SoC_EPDC_D15/ALT6_LCDIF_D15/SBC_PDISP_D15: P2.51 ; also on sheet 5
SoC_EPDC_PWRCOM: P1.77 ; also on sheet 1
SoC_EPDC_PWRSTAT/ALT5_GPIO2_31/SBC_CHRGR_nIRQ: P2.22 R62.1 ; also on sheet 1
SoC_GPIO1_2/ALT1_PWM2_OUT/SBC_LCDBCKLT_EN: P2.100 ; also on sheet 5
SoC_GPIO1_3/ALT0_GPIO1_3/SBC_CAM_SHUTTER: P2.92 ; also on sheet 1
SoC_GPIO1_5/ALT1_OTG1_PWR/SBC_OTG_PWREN: P2.6 R240.1 ; also on sheet 6
SoC_GPIO1_8/ALT4_I2C3_SCL/SBC_DVI_DDC_SCL: P1.45 ; also on sheet 1 5
SoC_GPIO1_9/ALT4_I2C3_SDA/SBC_DVI_DDC_SDA: P1.69 ; also on sheet 1 5
SoC_GPIO1_10/ALT4_I2C4_SCL/SBC_CARRIER_SCL: P2.1 U25.3(SCL) ; also on sheet 1 5 6
SoC_GPIO1_11/ALT4_I2C4_SDA/SBC_CARRIER_SDA: P2.3 U25.4(SDA) ; also on sheet 1 5 6
SoC_I2C1_SCL: P1.76 ; also on sheet 1
SoC_I2C1_SDA: P1.72 ; also on sheet 1
SoC_I2C2_SCL: P1.80 ; also on sheet 1
SoC_I2C2_SDA: P1.78 ; also on sheet 1
SoC_I2C3_SCL: P2.94 ; also on sheet 1
SoC_I2C3_SDA: P2.96 ; also on sheet 1
SoC_I2C4_SCL: P2.27 ; also on sheet 1
SoC_I2C4_SDA: P2.29 ; also on sheet 1
SoC_LCD1_CLK: P2.33 ; also on sheet 1
SoC_LCD1_DATA00/ALT0_LCDIF_D0/SBC_PDISP_D0/SRC_BT_CFG0: P2.87 ; also on sheet 5
SoC_LCD1_DATA01/ALT0_LCDIF_D1/SBC_PDISP_D1/SRC_BT_CFG1: P2.85 ; also on sheet 5
SoC_LCD1_DATA02/ALT0_LCDIF_D2/SBC_PDISP_D2/SRC_BT_CFG2: P2.83 ; also on sheet 5
SoC_LCD1_DATA03/ALT0_LCDIF_D3/SBC_PDISP_D3/SRC_BT_CFG3: P2.81 ; also on sheet 5
SoC_LCD1_DATA04/ALT3_CSI_VSYNC/SBC_CAM_VSYNC/SRC_BT_CFG4: P2.66 ; also on sheet 1
SoC_LCD1_DATA05/ALT3_CSI_HSYNC/SBC_CAM_HSYNC/SRC_BT_CFG5: P2.64 ; also on sheet 1
SoC_LCD1_DATA06/ALT3_CSI_PIXCLK/SBC_CAM_PCLK/SRC_BT_CFG6: P2.78 ; also on sheet 1
SoC_LCD1_DATA07/SRC_BT_CFG7: P2.45 ; also on sheet 1
SoC_LCD1_DATA08/SRC_BT_CFG8: P1.11 ; also on sheet 1
SoC_LCD1_DATA09/SRC_BT_CFG9: P1.13 ; also on sheet 1
SoC_LCD1_DATA10/SRC_BT_CFG10: P1.42 ; also on sheet 1
SoC_LCD1_DATA11/SRC_BT_CFG11: P1.56 ; also on sheet 1
SoC_LCD1_DATA12/ALT3_CSI_D5/SBC_CAM_D5/SRC_BT_CFG12: P1.68 ; also on sheet 1
SoC_LCD1_DATA13/ALT3_CSI_D4/SBC_CAM_D4/SRC_BT_CFG13: P1.64 ; also on sheet 1
SoC_LCD1_DATA14/ALT3_CSI_D3/SBC_CAM_D3/SRC_BT_CFG14: P1.66 ; also on sheet 1
SoC_LCD1_DATA15/ALT3_CSI_D2/SBC_CAM_D2/SRC_BT_CFG15: P1.60 ; also on sheet 1
SoC_LCD1_DATA16/ALT0_LCDIF_D16/SBC_PDISP_D16/SRC_BT_CFG16: P1.50 ; also on sheet 5
SoC_LCD1_DATA17/ALT0_LCDIF_D17/SBC_PDISP_D17/SRC_BT_CFG17: P2.47 ; also on sheet 5
SoC_LCD1_DATA18/ALT0_LCDIF_D18/SBC_PDISP_D18/SRC_BT_CFG18: P1.52 ; also on sheet 5
SoC_LCD1_DATA19/ALT0_LCDIF_D19/SBC_PDISP_D19/SRC_BT_CFG19: P1.54 ; also on sheet 5
SoC_LCD1_DATA20/ALT0_LCDIF_D20/SBC_PDISP_D20: P1.62 ; also on sheet 5
SoC_LCD1_DATA21/ALT0_LCDIF_D21/SBC_PDISP_D21: P2.37 ; also on sheet 5
SoC_LCD1_DATA22/ALT0_LCDIF_D22/SBC_PDISP_D22: P1.44 ; also on sheet 5
SoC_LCD1_DATA23/ALT0_LCDIF_D23/SBC_PDISP_D23: P1.40 ; also on sheet 5
SoC_LCD1_ENABLE: P1.28 ; also on sheet 1
SoC_LCD1_HSYNC: P1.48 ; also on sheet 1
SoC_LCD1_RESET/ALT5_GPIO3_4/SBC_CAM_RESET: P2.80 ; also on sheet 1
SoC_LCD1_VSYNC: P2.41 ; also on sheet 1
SoC_MIPI_CSI_CLK_N: P1.55 ; also on sheet 1
SoC_MIPI_CSI_CLK_P: P1.53 ; also on sheet 1
SoC_MIPI_CSI_D0_N: P1.43 ; also on sheet 1
SoC_MIPI_CSI_D0_P: P1.41 ; also on sheet 1
SoC_MIPI_CSI_D1_N: P1.49 ; also on sheet 1
SoC_MIPI_CSI_D1_P: P1.47 ; also on sheet 1
SoC_MIPI_DSI_CLK_N: P1.73 ; also on sheet 5
SoC_MIPI_DSI_CLK_P: P1.71 ; also on sheet 5
SoC_MIPI_DSI_D0_N: P1.61 ; also on sheet 5
SoC_MIPI_DSI_D0_P: P1.59 ; also on sheet 5
SoC_MIPI_DSI_D1_N: P1.67 ; also on sheet 5
SoC_MIPI_DSI_D1_P: P1.65 ; also on sheet 5
SoC_ONOFF: P1.97 ; also on sheet 4
SoC_PCIE_REFCLKIN_N: P2.42 ; also on sheet 1 6
SoC_PCIE_REFCLKIN_P: P2.40 ; also on sheet 1 6
SoC_PCIE_REFCLKOUT_N: P2.46 ; also on sheet 6
SoC_PCIE_REFCLKOUT_P: P2.48 ; also on sheet 6
SoC_PCIE_RX_N: P2.52 ; also on sheet 6
SoC_PCIE_RX_P: P2.54 ; also on sheet 6
SoC_PCIE_TX_N: P2.58 ; also on sheet 6
SoC_PCIE_TX_P: P2.60 ; also on sheet 6
SoC_SD1_CD_B/ALT0_SD1_CD_B/SBC_SDCARD_CD: P1.82 ; also on sheet 4
SoC_SD1_CLK/ALT0_SD1_CLK/SBC_SDCARD_CLK: P2.4 ; also on sheet 4
SoC_SD1_CMD/ALT0_SD1_CMD/SBC_SDCARD_CMD: P2.12 ; also on sheet 4
SoC_SD1_DATA0/ALT0_SD1_D0/SBC_SDCARD_D0: P2.16 ; also on sheet 4
SoC_SD1_DATA1/ALT0_SD1_D1/SBC_SDCARD_D1: P2.24 ; also on sheet 4
SoC_SD1_DATA2/ALT0_SD1_D2/SBC_SDCARD_D2: P2.10 ; also on sheet 4
SoC_SD1_DATA3/ALT0_SD1_D3/SBC_SDCARD_D3: P2.8 ; also on sheet 4
SoC_SD1_RESET_B: P2.18 ; also on sheet 1
SoC_SD1_WP/ALT0_SD1_WP/SBC_SDCARD_WP: P2.49 ; also on sheet 1
SoC_UART1_RXD/ALT0_UART1_RX/SBC_CONSOLE_RX: P2.84 ; also on sheet 4
SoC_UART1_TXD/ALT0_UART1_TX/SBC_CONSOLE_TX: P2.82 ; also on sheet 4
SoC_USB_OTG1_CHD_B: P2.56 R237.1
SoC_USB_OTG1_DN/SoC_USB_OTG_DN: P2.34 ; also on sheet 6
SoC_USB_OTG1_DP/SoC_USB_OTG_DP: P2.36 ; also on sheet 6
SoC_USB_OTG1_ID/SoC_USB_OTG_ID: P2.5 ; also on sheet 6
SoC_USB_OTG2_DN/SoC_USB_HOST_DN: P2.30 ; also on sheet 1
SoC_USB_OTG2_DP/SoC_USB_HOST_DP: P2.28 ; also on sheet 1
SWBAT: L14.1 U21.B1(SW) U21.B2(SW)
TS_XN: P1.81 ; also on sheet 1 5
TS_XP: P1.79 ; also on sheet 1 5
TS_YN: P1.85 ; also on sheet 1 5
TS_YP: P1.83 ; also on sheet 1 5
USBH_DN1: P2.21 ; also on sheet 6
USBH_DN2: P2.9 ; also on sheet 6
USBH_DN3: P2.15 ; also on sheet 6
USBH_DP1: P2.23 ; also on sheet 6
USBH_DP2: P2.11 ; also on sheet 6
USBH_DP3: P2.17 ; also on sheet 6
V_RTC: BT1.1(POS) D9.CATHODE E8.3
VCOIN: BH1.2(PLUS) D9.ANODE
VDC_5V: C86.1 C111.1 L13.2 Q14.3(Drain) R46.1 R82.2 R94.1 R104.1 R235.2 R273.2 R283.1 U25.21(IN)
VDC_IN: C87.1 C88.1 C89.1 C257.1 FB7.2 R43.1 R252.2 R262.2 R274.2 S5.2 U20.2(Vin) U22.2(Vin)
VDCIN_OFF: Q4.1(G) Q29.3(D) R76.2
VDCIN_ON: Q29.1(G) R31.2 R274.1
VNDCIN_OFF: Q3.1(G) R74.2 R262.1
VSB_1V5: C135.1 R92.1 R168.2 U26.7(Vout1) U26.8(Vout2) ; also on sheet 1 6
VSB_1V5_EN: R164.1 R257.2 R258.1 U26.4(EN)
VSB_1V8: C136.1 R87.1 R165.1 R169.2 U31.7(Vout1) U31.8(Vout2) ; also on sheet 1
VSB_1V8_PGOOD: R165.2 R260.2 U31.3(PGOOD)
VSB_2V8: C137.1 R91.1 R166.1 R170.2 U32.7(Vout1) U32.8(Vout2) ; also on sheet 1
VSB_2V8_EN: R163.1 R259.2 R260.1 U32.4(EN)
VSB_2V8_PGOOD: R166.2 R258.2 U32.3(PGOOD)
VSB_3V3_AW: C23.1 C27.1 C31.1 C32.1 C33.1 C34.1 C35.1 C36.1 C48.1 C49.1 C52.1 C53.1 C64.1 C65.1 C66.1 C67.1 C68.1 C69.1 C70.1 C71.1 C72.1 C75.1 C76.1 C77.1 C78.1 C119.1 C120.1 C121.1 Q15.2(Source) Q16.2(Source) R41.2 R227.1 R264.2 R280.2 ; also on sheet 1 4 5 6
VSB_3V3_DC: C106.1 L16.2 Q16.3(Drain) R86.2 R93.1 R103.2 R247.1 R279.1 R288.1
VSB_3V3_DC_EN: R235.1 R282.2 U22.7(EN)
VSB_3V3_nDC: C255.1 Q15.3(Drain) R84.1 R95.1 R100.2 R232.2 R256.2 R266.2 R270.2 U39.7(Vout1) U39.8(Vout2) ; also on sheet 4
VSB_3V3_nDC_EN: R234.1 R281.2 U39.4(EN)
VSB_BOOST5V_EN: R261.2 R266.1 U21.B3(EN)
VSYS: C14.1 C15.1 C16.1 C17.2 C18.2 C19.1 C20.1 C21.2 C96.1 C97.1 C98.1 C115.1 C130.1 C131.1 C132.1 C254.1 L14.2 L17.2 P1.1 P1.2 P1.3 P1.4 P1.5 P1.6 P1.7 P1.8 P1.9 P1.16 P1.22 Q3.2(S) Q12.1(S) Q12.2(S) Q12.3(S) R56.2 R85.1 R88.2 R163.2 R164.2 R203.1 R228.1 R229.1 R234.2 R284.1 U7.5(VCC) U21.A3(VIN) U25.13(SYS) U25.14(SYS) U26.1(Vin1) U26.2(Vin2) U31.1(Vin1) U31.2(Vin2) U32.1(Vin1) U32.2(Vin2) U37.5(VCC) U39.1(Vin1) U39.2(Vin2) U42.5(VCC) ; also on sheet 4 6
WLANBYP_SoC_SD2_CLK: P1.29 ; also on sheet 1
WLANBYP_SoC_SD2_CMD: P1.37 ; also on sheet 1
WLANBYP_SoC_SD2_DATA0: P1.25 ; also on sheet 1
WLANBYP_SoC_SD2_DATA1: P1.31 ; also on sheet 1
WLANBYP_SoC_SD2_DATA2: P1.33 ; also on sheet 1
WLANBYP_SoC_SD2_DATA3: P1.35 ; also on sheet 1

Not connected (* = marked no-connect by the designer): J6 2*; Q32 3(D2)* 4(S2)* 5(G2)*; U25 1(NC)*; U26 3(PGOOD)*; U39 3(PGOOD)*

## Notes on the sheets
sheet 7
- VSB_5V_AW
  SOURCE
- DC-to-5.25V (5VDC_SOURCE)
- DC INPUT
- DNP
- BOOST_5V source
- VIN_DC(min) = 5.3V
  VIN_DC(max) = 16V
- DNP
- DNP
- DNP
- DNP
- Vout=Vfb*(1+Rt/Rb)=0.92*(1+44.2/10)=4.9864V.
  Note: in case VDC_IN is @ minimum voltage
  (5.3V),
   BQ_INSRC(max) is @ 5.3*0.8 = 4.24V,  (still
  valid for  BQ24161 input)
- DNP
- DNP
- DNP
- DNP
- DNP
- DNP
- DNP
- RAIL DISCHARGE
  CIRCUITRY
- AUTOMATIC POWER SOURCE SWITCHING
  BETWEEN BATTERY / DC / USB-OTG PORT.
  & BATTERY CHARGER
- i.MX7 boot-rom will enable charger detection during boot if all of the following conditions are met:
  1. LPB_BOOT fuse value is 0b10 or 0b11 (0b00 by default)
  2. BT_LPB_POLARITY is 0b0 (0b0 by default).
  3. i.MX7 GPIO_3 pin is low during boot (low by default)
  In case a charger is detected, the USB_OTG1_CHD_B
   OD signal might source GND (depends on i.MX7 bootrom). otherwise, this is a high-Z pin.
- BQ24161 minimum output
   voltage @ VCC_CM = 3.4V
- DNP
- DNP
- DNP
- DNP
- 7-bit I2C address:
  0b110,1011
- Assuming NTC properties
- DNP
- NTC resiststance
- 10K
- Battery temperature
- 25degC
- 6K
- 40degC
- 25K
- 0degC
- CHARGER LED
- BQ24161 USB input initial current
  limit is set by PSEL pin logic level
  PSEL = 1 (Vpsel > 1.4v) ==> limit is 100mA
  PSEL = 0 (Vpsel < 0.4v) ==> limit is 1500mA
  Once an I2C write into BQ24161 is done, the PSEL has
  no effect on the USB input current limit until the
  watchdog imer expires.
- VSB_3V3_AW
  SOURCE
- VSB_1V5, VSB_1V8 & VCC_2V8 sources
- PERIPHERAL VOLTAGE
  ENABLE LOGIC
- VSB_3V3_nDC source
- Vout=Vfb*(1+Rt/Rb)=0.8*(1+31.6/10)=3.328V
- Vout=Vfb*(1+Rt/Rb)=0.8*(1+9.1/10)=1.528V
- DNP
- DNP
- DNP
- DNP
- DNP
- U42 Vih:
  =======
  1.65V<VCC<1.95V = 0.65Vcc =
  1.0725V..1.2675V
  3V<VCC<3.6V = 2V
  4.5V<VCC<5.5V = 0.7Vcc =
  3.15V..3.85V
- VSB_3V3_DC SOURCE
- Vout=Vfb*(1+Rt/Rb)=0.8*(1+9.1/10)=1.528V
- DNP
- Source of the onboard 3.3V power rail
  used for most onboard integrated
  circuitry
- Vout=Vfb*(1+Rt/Rb)=
  0.92*(1+43.2/16.5)=3.3287V.
- DNP
- DNP
- DNP
- RTC BATTERY
- DNP
- DNP
- DNP
- DNP
- DNP
- RTC function:
   Enable:
      Short pins 2 <-> 3
   Disable:
       Short pins 2 <-> 1
- Vout=Vfb*(1+Rt/Rb)=0.8*(1+9.1/10)=1.528V
- DNP
- DNP
sheet 8
- Stitching CAPs
- BOOT_CFG8
- BOOT_CFG9
- UART2_TX is ALT4
- BOOT_CFG10
- UART2_RTS is ALT4
- BOOT_CFG16
- BOOT_CFG18
- BOOT_CFG19
- BOOT_CFG11
- BOOT_CFG15
- BOOT_CFG13
- BOOT_CFG12
- BOOT_CFG14
- ECSPI3_MOSI is ALT3
- ECSPI3_SS3 is ALT3
- ECSPI3_MISO is ALT3
- ECSPI3_SCLK is ALT3
- ECSPI3_SS0 is ALT3
- DNP
- UART5_RTS is ALT1
- UART5_CTS is ALT1
- BOOT_CFG0
- BOOT_CFG1
- BOOT_CFG2
- CONSOLE
- BOOT_CFG3
- CONSOLE
- BOOT_CFG6
- UCM-iMX7 Mounting Hole
- BOOT_CFG4
- BOOT_CFG5
- BOOT_CFG17
- BOOT_CFG7
- UART2_CTS is ALT4
- UART2_RX is ALT4
- UART5_TX is ALT1
- UART5_RX is ALT1
- Main power not from 12V-DC
- Main power from 12V-DC
- Multifunctional nets naming conventions
- 1. Net connected between i.MX7 {mux mode setting undefined} and SODIMM connector:
- SoC_{pin name}
- SOM supply enabled
- 2. Nets connected between i.MX7 {specific mux mode requested} and SODIMM connector:
- Peripheral supplies enabled
- SoC_{pin name}/ALT{required mux mode #}_{required mux name}/SBC_{SB-SOM function / pin name}
- 3. Nets connected between i.MX7 {specific mux mode requested} and onboard peripheral:
- SoC_{pin name}/ALT{required mux mode #}_{required mux name}/{onboard peripheral short name}_{onboard peripheral pin function}
- 4. Nets connected between i.MX7  {mux mode setting undefined} and SODIMM connector, bypassing onboard peripheral,
  unless name defined by the peripheral being bypassed:
- {onboard peripheral short name}BYP_SoC_{pin name}
- 5. Nets sampled at i.MX7 boot (and then used for other function during normal operation):
- {net name accoding to above rules}/{function during boot}
